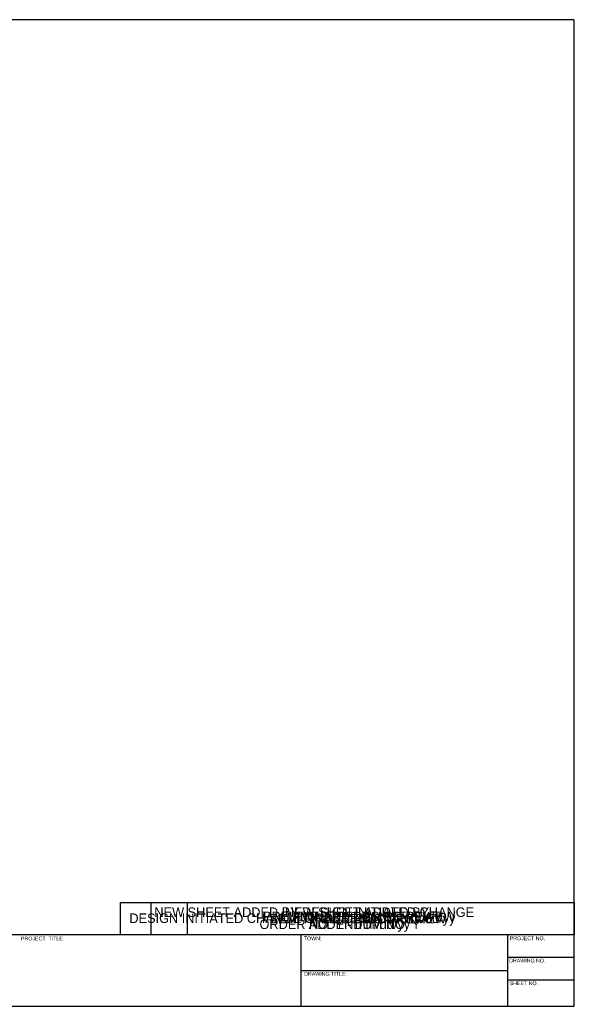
# Model space of a CAD drawing. Extents: x 0 to 31.8, y -0.5 to 20.8.
# Drawn here: x 20.1 to 31.75, y 0 to 20.75 of the extents above; entities that cross this region are included whole.
import ezdxf

# ---------------------------------------------------------------- set-up
doc = ezdxf.new("R2010")
doc.units = 0
for name, color, linetype in [('CT_Border_Perimeter_Shape', 7, 'Continuous'), ('CT_Note_Addendum', 7, 'Continuous'), ('CT_Note_Design_Initiated_Change_Order', 7, 'Continuous'), ('CT_Note_Final_Design_Review', 7, 'Continuous'), ('CT_Note_New_Sheet_by_Addendum', 7, 'Continuous'), ('CT_Note_New_Sheet_by_Design_Initiated_Change_Order', 7, 'Continuous'), ('CT_Note_Preliminary_Design_Review', 7, 'Continuous'), ('CT_Note_Semi_Final_Design_Review', 7, 'Continuous'), ('CT_Title_Block_Linework', 7, 'Continuous'), ('CT_Title_Block_Text', 7, 'Continuous')]:
    doc.layers.add(name, color=color, linetype=linetype)

msp = doc.modelspace()

# ---------------------------------------------------------------- linework, layer by layer
at = {"layer": 'CT_Border_Perimeter_Shape'}
msp.add_lwpolyline([(0, 0), (31.75, 0), (31.75, 20.75), (0, 20.75)], close=True, dxfattribs=at)
at = {"layer": 'CT_Note_Addendum'}
msp.add_lwpolyline([(23.621, 2.186), (31.75, 2.186), (31.75, 1.5), (23.621, 1.5)], close=True, dxfattribs=at)
msp.add_lwpolyline([(23.621, 2.186), (31.75, 2.186), (31.75, 1.5), (23.621, 1.5)], close=True, dxfattribs=at)
at = {"layer": 'CT_Note_Design_Initiated_Change_Order'}
msp.add_lwpolyline([(22.217, 2.186), (31.75, 2.186), (31.75, 1.5), (22.217, 1.5)], close=True, dxfattribs=at)
msp.add_lwpolyline([(22.217, 2.186), (31.75, 2.186), (31.75, 1.5), (22.217, 1.5)], close=True, dxfattribs=at)
at = {"layer": 'CT_Note_Final_Design_Review'}
msp.add_lwpolyline([(23.621, 2.186), (31.75, 2.186), (31.75, 1.5), (23.621, 1.5)], close=True, dxfattribs=at)
at = {"layer": 'CT_Note_New_Sheet_by_Addendum'}
msp.add_lwpolyline([(23.621, 2.186), (31.75, 2.186), (31.75, 1.5), (23.621, 1.5)], close=True, dxfattribs=at)
msp.add_lwpolyline([(23.621, 2.186), (31.75, 2.186), (31.75, 1.5), (23.621, 1.5)], close=True, dxfattribs=at)
at = {"layer": 'CT_Note_New_Sheet_by_Design_Initiated_Change_Order'}
msp.add_lwpolyline([(22.858, 2.186), (31.75, 2.186), (31.75, 1.5), (22.858, 1.5)], close=True, dxfattribs=at)
msp.add_lwpolyline([(22.858, 2.186), (31.75, 2.186), (31.75, 1.5), (22.858, 1.5)], close=True, dxfattribs=at)
at = {"layer": 'CT_Note_Preliminary_Design_Review'}
msp.add_lwpolyline([(23.621, 2.186), (31.75, 2.186), (31.75, 1.5), (23.621, 1.5)], close=True, dxfattribs=at)
at = {"layer": 'CT_Note_Semi_Final_Design_Review'}
msp.add_lwpolyline([(23.621, 2.186), (31.75, 2.186), (31.75, 1.5), (23.621, 1.5)], close=True, dxfattribs=at)
msp.add_lwpolyline([(23.621, 2.186), (31.75, 2.186), (31.75, 1.5), (23.621, 1.5)], close=True, dxfattribs=at)
at = {"layer": 'CT_Title_Block_Linework'}
for p, q in [((31.75, 1.5), (0, 1.5)), ((26.004, 1.5), (26.004, 0)), ((30.351, 1.5), (30.351, 0)), ((30.351, 1.031), (31.75, 1.031)), ((26.004, 0.75), (30.351, 0.75)), ((30.351, 0.556), (31.75, 0.556))]:
    msp.add_line(p, q, dxfattribs=at)

# ---------------------------------------------------------------- texts
at = {"layer": 'CT_Note_Addendum'}
msp.add_text('ADDENDUM NO. Y', height=0.2, dxfattribs=at).set_placement((26.475, 1.741))
at = {"layer": 'CT_Note_Design_Initiated_Change_Order'}
msp.add_text('DESIGN INITIATED CHANGE ORDER NO. Y - mm/dd/yy', height=0.2, dxfattribs=at).set_placement((22.403, 1.752))
at = {"layer": 'CT_Note_Final_Design_Review'}
msp.add_text('FINAL DESIGN REVIEW', height=0.2, dxfattribs=at).set_placement((25.825, 1.78))
at = {"layer": 'CT_Note_New_Sheet_by_Addendum'}
for s, p in [('NEW SHEET ADDED BY', (25.67, 1.879)), ('ADDENDUM NO. Y', (26.171, 1.625))]:
    msp.add_text(s, height=0.2, dxfattribs=at).set_placement(p)
at = {"layer": 'CT_Note_New_Sheet_by_Design_Initiated_Change_Order'}
for s, p in [('NEW SHEET ADDED BY DESIGN INITIATED CHANGE', (22.928, 1.879)), ('ORDER NO. Y - mm/dd/yy', (25.137, 1.625))]:
    msp.add_text(s, height=0.2, dxfattribs=at).set_placement(p)
at = {"layer": 'CT_Note_Preliminary_Design_Review'}
msp.add_text('PRELIMINARY DESIGN REVIEW', height=0.2, rotation=360, dxfattribs=at).set_placement((25.21, 1.789))
at = {"layer": 'CT_Note_Semi_Final_Design_Review'}
msp.add_text('SEMI FINAL DESIGN REVIEW', height=0.2, dxfattribs=at).set_placement((25.346, 1.744))
at = {"layer": 'CT_Title_Block_Text'}
for s, p in [('PROJECT  TITLE:', (20.126, 1.385)), ('TOWN:', (26.069, 1.388)), ('PROJECT NO.', (30.394, 1.39)), ('DRAWING NO.', (30.383, 0.921)), ('DRAWING TITLE:', (26.075, 0.641)), ('SHEET NO.', (30.393, 0.444))]:
    msp.add_text(s, height=0.08, rotation=360, dxfattribs=at).set_placement(p)

doc.saveas('drawing.dxf')
